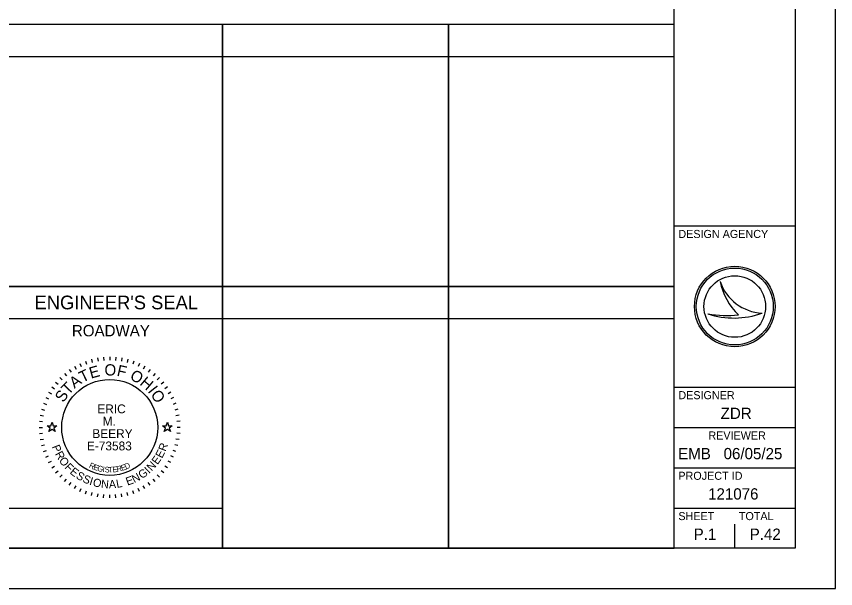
# Model space of a CAD drawing. Extents: x 0 to 42.5, y 0 to 22.
# Drawn here: x 23.84 to 34, y 0 to 7.1 of the extents above; entities that cross this region are included whole.
import ezdxf

# ---------------------------------------------------------------- set-up
doc = ezdxf.new("R2010")
doc.units = 0
for name, color, linetype in [('SH_Border', 7, 'Continuous'), ('SH_Cut_Line', 7, 'Continuous'), ('SH_Data', 7, 'Continuous'), ('SH_Seal', 7, 'Continuous')]:
    doc.layers.add(name, color=color, linetype=linetype)

msp = doc.modelspace()

# ---------------------------------------------------------------- linework, layer by layer
at = {"layer": 'SH_Border'}
for p, q in [((32, 0.5), (32, 21.5)), ((32, 4.5), (33.5, 4.5)), ((32, 2.5), (33.5, 2.5)), ((32, 2), (33.5, 2)), ((32, 1.5), (33.5, 1.5)), ((32, 1), (33.5, 1))]:
    msp.add_line(p, q, dxfattribs=at)
msp.add_lwpolyline([(1.5, 21.5), (33.5, 21.5), (33.5, 0.5), (1.5, 0.5)], close=True, dxfattribs=at)
at = {"layer": 'SH_Cut_Line'}
msp.add_lwpolyline([(0, 0), (34, 0), (34, 22), (0, 22)], close=True, dxfattribs=at)
at = {"layer": 'SH_Data'}
for p, q in [((23.6, 6.6), (26.4, 6.6)), ((26.4, 6.6), (29.2, 6.6)), ((29.2, 6.6), (32, 6.6)), ((32.567, 3.81), (32.567, 3.81)), ((23.6, 3.75), (26.4, 3.75)), ((26.4, 3.75), (26.4, 0.5)), ((32.75, 3.5), (32.75, 3.5)), ((32.417, 3.41), (32.417, 3.41)), ((33.087, 3.419), (33.087, 3.419)), ((23.6, 3.35), (26.4, 3.35)), ((23.6, 3.35), (26.4, 3.35)), ((26.4, 3.35), (29.2, 3.35)), ((29.2, 3.35), (32, 3.35)), ((32.75, 0.5), (32.75, 0.8)), ((32.375, 0.675), (32.375, 0.675)), ((23.6, 0.5), (26.4, 0.5))]:
    msp.add_line(p, q, dxfattribs=at)
for points in [[(26.4, 7), (23.6, 7), (23.6, 3.75), (26.4, 3.75)], [(29.2, 7), (26.4, 7), (26.4, 3.75), (29.2, 3.75)], [(32, 7), (29.2, 7), (29.2, 3.75), (32, 3.75)], [(26.4, 3.75), (23.6, 3.75), (23.6, 0.5), (26.4, 0.5)], [(29.2, 3.75), (26.4, 3.75), (26.4, 0.5), (29.2, 0.5)], [(32, 3.75), (29.2, 3.75), (29.2, 0.5), (32, 0.5)], [(23.6, 0.5), (23.6, 1), (26.4, 1), (26.4, 0.5)]]:
    msp.add_lwpolyline(points, close=True, dxfattribs=at)
for radius in [0.5, 0.477, 0.477, 0.382]:
    msp.add_circle((32.75, 3.5), radius, dxfattribs=at)
for centre, radius, start, end in [((33.116, 3.998), 0.58, 198.9257, 198.9319), ((33.347, 3.97), 0.796, 191.6379, 191.6421), ((33.116, 3.998), 0.58, 198.9319, 267.1657), ((33.347, 3.97), 0.796, 191.6421, 226.0947), ((32.739, 4.37), 1.013, 251.4576, 290.0832), ((32.648, 4.654), 1.266, 259.4964, 259.4995), ((32.739, 4.37), 1.013, 251.4527, 251.4576), ((32.648, 4.654), 1.266, 259.4995, 276.6672)]:
    msp.add_arc(centre, radius, start, end, dxfattribs=at)
at = {"layer": 'SH_Seal'}
for p, q in [((24.774, 2.845), (24.784, 2.807)), ((24.848, 2.862), (24.855, 2.822)), ((24.924, 2.872), (24.927, 2.832)), ((25, 2.875), (25, 2.835)), ((25.076, 2.872), (25.073, 2.832)), ((25.152, 2.862), (25.145, 2.822)), ((25.226, 2.845), (25.216, 2.807)), ((24.563, 2.758), (24.583, 2.723)), ((24.63, 2.793), (24.647, 2.757)), ((24.701, 2.822), (24.714, 2.785)), ((25.299, 2.822), (25.286, 2.785)), ((25.37, 2.793), (25.353, 2.757)), ((25.437, 2.758), (25.417, 2.723)), ((24.438, 2.67), (24.463, 2.64)), ((24.498, 2.717), (24.521, 2.684)), ((25.502, 2.717), (25.479, 2.684)), ((25.562, 2.67), (25.537, 2.64)), ((24.33, 2.562), (24.36, 2.537)), ((24.381, 2.619), (24.41, 2.59)), ((25.619, 2.619), (25.59, 2.59)), ((25.67, 2.562), (25.64, 2.537)), ((24.283, 2.502), (24.316, 2.479)), ((25.717, 2.502), (25.684, 2.479)), ((24.207, 2.37), (24.243, 2.353)), ((24.242, 2.438), (24.277, 2.418)), ((25.758, 2.438), (25.723, 2.418)), ((25.793, 2.37), (25.757, 2.353)), ((24.178, 2.299), (24.215, 2.286)), ((25.822, 2.299), (25.785, 2.286)), ((24.138, 2.152), (24.178, 2.145)), ((24.155, 2.226), (24.193, 2.216)), ((25.845, 2.226), (25.807, 2.216)), ((25.862, 2.152), (25.822, 2.145)), ((24.128, 2.076), (24.168, 2.073)), ((25.872, 2.076), (25.832, 2.073)), ((24.125, 2), (24.165, 2)), ((25.875, 2), (25.835, 2)), ((24.128, 1.924), (24.168, 1.927)), ((24.138, 1.848), (24.178, 1.855)), ((25.862, 1.848), (25.822, 1.855)), ((25.872, 1.924), (25.832, 1.927)), ((24.155, 1.774), (24.193, 1.784)), ((25.845, 1.774), (25.807, 1.784)), ((24.178, 1.701), (24.215, 1.714)), ((24.207, 1.63), (24.243, 1.647)), ((25.793, 1.63), (25.757, 1.647)), ((25.822, 1.701), (25.785, 1.714)), ((24.242, 1.563), (24.277, 1.583)), ((25.758, 1.563), (25.723, 1.583)), ((24.283, 1.498), (24.316, 1.521)), ((24.33, 1.438), (24.36, 1.463)), ((25.67, 1.438), (25.64, 1.463)), ((25.717, 1.498), (25.684, 1.521)), ((24.381, 1.381), (24.41, 1.41)), ((24.438, 1.33), (24.463, 1.36)), ((25.562, 1.33), (25.537, 1.36)), ((25.619, 1.381), (25.59, 1.41)), ((24.498, 1.283), (24.521, 1.316)), ((24.563, 1.242), (24.583, 1.277)), ((24.63, 1.207), (24.647, 1.243)), ((25.37, 1.207), (25.353, 1.243)), ((25.437, 1.242), (25.417, 1.277)), ((25.502, 1.283), (25.479, 1.316)), ((24.701, 1.178), (24.714, 1.215)), ((24.774, 1.155), (24.784, 1.193)), ((24.848, 1.138), (24.855, 1.178)), ((24.924, 1.128), (24.927, 1.168)), ((25, 1.125), (25, 1.165)), ((25.076, 1.128), (25.073, 1.168)), ((25.152, 1.138), (25.145, 1.178)), ((25.226, 1.155), (25.216, 1.193)), ((25.299, 1.178), (25.286, 1.215))]:
    msp.add_line(p, q, dxfattribs=at)
for points in [[(24.224, 2.02), (24.271, 2.02), (24.285, 2.065), (24.299, 2.02), (24.346, 2.02), (24.308, 1.992), (24.323, 1.948), (24.285, 1.975), (24.247, 1.948), (24.262, 1.992)], [(25.654, 2.02), (25.701, 2.02), (25.715, 2.065), (25.729, 2.02), (25.776, 2.02), (25.738, 1.992), (25.753, 1.948), (25.715, 1.975), (25.677, 1.948), (25.692, 1.992)]]:
    msp.add_lwpolyline(points, close=True, dxfattribs=at)
msp.add_circle((25, 2), 0.595, dxfattribs=at)

# ---------------------------------------------------------------- texts
at = {"layer": 'SH_Data'}
for s, height, p in [('DESIGN AGENCY', 0.1, (32.05, 4.35)), ("ENGINEER'S SEAL", 0.17, (24.068, 3.465)), ('ROADWAY', 0.14, (24.531, 3.13)), ('DESIGNER', 0.1, (32.05, 2.35)), ('ZDR', 0.14, (32.575, 2.105)), ('REVIEWER', 0.1, (32.422, 1.85)), ('EMB', 0.14, (32.047, 1.605)), ('06/05/25', 0.14, (32.611, 1.605)), ('PROJECT ID', 0.1, (32.05, 1.35)), ('121076', 0.14, (32.419, 1.105)), ('SHEET', 0.1, (32.05, 0.85)), ('TOTAL', 0.1, (32.8, 0.85)), ('P.1', 0.14, (32.24, 0.605)), ('P.42', 0.14, (32.935, 0.605))]:
    msp.add_text(s, height=height, dxfattribs=at).set_placement(p)
at = {"layer": 'SH_Seal'}
for s, height, rotation, p in [('E', 0.14, 15.7571, (24.768, 2.604)), ('O', 0.14, 359.7812, (24.935, 2.644)), ('F', 0.14, 347.4362, (25.081, 2.642)), ('T', 0.14, 25.7167, (24.662, 2.552)), ('O', 0.14, 332.2586, (25.24, 2.602)), ('T', 0.14, 46.4344, (24.488, 2.396)), ('A', 0.14, 36.4747, (24.563, 2.478)), ('H', 0.14, 319.9136, (25.363, 2.536)), ('S', 0.14, 57.1924, (24.428, 2.301)), ('I', 0.14, 308.367, (25.466, 2.448)), ('O', 0.14, 303.1491, (25.502, 2.409)), ('P', 0.1, 291.494, (24.282, 1.762)), ('E', 0.1, 61.9951, (25.648, 1.61)), ('R', 0.1, 69.2322, (25.692, 1.695)), ('R', 0.1, 298.7311, (24.319, 1.672)), ('O', 0.1, 306.4666, (24.365, 1.588)), ('E', 0.1, 54.758, (25.593, 1.531)), ('F', 0.1, 314.7068, (24.434, 1.498)), ('R', 0.07, 334.487, (24.737, 1.505)), ('E', 0.07, 341.04, (24.791, 1.48)), ('G', 0.07, 347.4752, (24.841, 1.462)), ('R', 0.07, 11.9184, (25.092, 1.447)), ('E', 0.07, 17.6836, (25.15, 1.46)), ('D', 0.07, 23.3052, (25.201, 1.477)), ('N', 0.1, 47.0224, (25.52, 1.451)), ('E', 0.1, 321.4393, (24.498, 1.435)), ('S', 0.1, 328.6764, (24.574, 1.375)), ('I', 0.07, 353.7858, (24.909, 1.447)), ('S', 0.07, 356.8926, (24.936, 1.443)), ('T', 0.07, 3.0061, (24.986, 1.439)), ('E', 0.07, 6.0117, (25.039, 1.441)), ('N', 0.1, 27.3113, (25.304, 1.308)), ('G', 0.1, 35.0469, (25.398, 1.357)), ('I', 0.1, 43.287, (25.487, 1.421)), ('S', 0.1, 335.9134, (24.656, 1.327)), ('I', 0.1, 343.1505, (24.741, 1.29)), ('O', 0.1, 346.8859, (24.784, 1.275)), ('N', 0.1, 355.1261, (24.889, 1.252)), ('A', 0.1, 2.8617, (24.992, 1.244)), ('L', 0.1, 10.0987, (25.089, 1.249)), ('E', 0.1, 20.0742, (25.221, 1.277))]:
    msp.add_text(s, height=height, rotation=rotation, dxfattribs=at).set_placement(p)
for s, p in [('ERIC', (24.847, 2.175)), ('M.', (24.913, 2.022)), ('BEERY', (24.785, 1.868)), ('E-73583', (24.718, 1.715))]:
    msp.add_text(s, height=0.11, dxfattribs=at).set_placement(p)

doc.saveas('drawing.dxf')
